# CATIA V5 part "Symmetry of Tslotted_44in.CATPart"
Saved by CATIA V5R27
Part number: Symmetry of Tslotted_44in
Bounding box of the stored display mesh (mm): x -19.056 to 19.056, y -19.056 to 19.056, z -1524 to -404
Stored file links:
  \\triton.meca.polymtl.ca\usagers\zaoue\profiles\Desktop\varm_ass\structure prismatique\Symmetry of Tslotted_44in.CATPart
  \\triton.meca.polymtl.ca\usagers\zaoue\profiles\Desktop\varm_ass\structure prismatique\Alu_Tslot_44in.CATPart
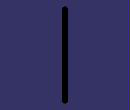
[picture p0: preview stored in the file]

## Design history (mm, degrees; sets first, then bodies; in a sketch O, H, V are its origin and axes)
Body1 (main body)
  Body2 "Corps du corps principal d'origine"
    Solid1: linked copy from another document
  Assemble1: tool Body2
